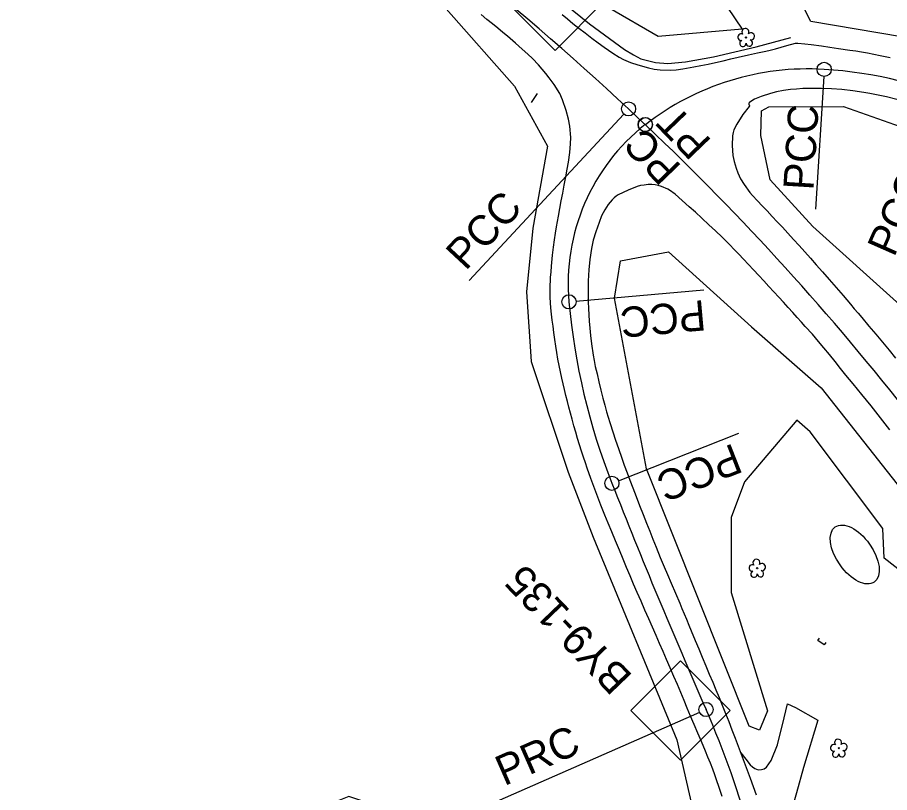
# Model space of a CAD drawing. Extents: x 473158 to 477500, y 500738 to 505114.
# Drawn here: x 475094.4 to 475555.3, y 502314.3 to 502723.9 of the extents above; entities that cross this region are included whole.
import ezdxf

# ---------------------------------------------------------------- set-up
doc = ezdxf.new("R2010")
doc.units = 0
for name, color, linetype in [('CTL Secondary Horizontal and Vertical CELL', 7, 'Continuous'), ('CTL Secondary Horizontal and Vertical Text', 7, 'Continuous'), ('Exist Guardrail', 7, 'Continuous'), ('Exist Horizontal Alignment', 7, 'Continuous'), ('Exist Other Culture Area Outline', 7, 'Continuous'), ('Exist Other Culture Sign', 7, 'Continuous'), ('Exist Roads EOP', 7, 'Continuous'), ('Exist Roads Soil', 7, 'Continuous'), ('Exist Vegetation Tree CELL', 7, 'Continuous'), ('Exist Vegetation Woods Line', 7, 'Continuous')]:
    doc.layers.add(name, color=color, linetype=linetype)

msp = doc.modelspace()

# ---------------------------------------------------------------- linework, layer by layer
at = {"layer": 'CTL Secondary Horizontal and Vertical CELL'}
msp.add_line((475444.73, 502357.61), (475444.73, 502357.61), dxfattribs=at)
for points in [[(475352.26, 502732.72), (475378.47, 502758.92), (475404.72, 502732.67), (475378.52, 502706.47)], [(475418.66, 502357.7), (475444.86, 502383.91), (475471.11, 502357.66), (475444.91, 502331.45)]]:
    msp.add_lwpolyline(points, close=True, dxfattribs=at)
at = {"layer": 'Exist Guardrail'}
msp.add_lwpolyline([(475217.33, 502867.76), (475216.44, 502862.82), (475216.67, 502859.88), (475217.59, 502857.13), (475219.31, 502854.45), (475221.83, 502851.72), (475229.36, 502844.29), (475232.25, 502841.82), (475257.72, 502824.07), (475280.52, 502807.76), (475315.04, 502782.65), (475345.62, 502761.25), (475378.34, 502735.51), (475396.81, 502720.46), (475415.24, 502707), (475419.92, 502704.07), (475423.92, 502701.99), (475431.54, 502699.97), (475438.09, 502699.45), (475447.54, 502700.48), (475462.27, 502702.99), (475484.79, 502708.35), (475503.22, 502713.19)], dxfattribs=at)
at = {"layer": 'Exist Horizontal Alignment'}
for p, q in [((475520.51, 502692.66), (475516.17, 502622.65)), ((475414.82, 502672.8), (475333.05, 502584.93)), ((475389.59, 502573.92), (475457.23, 502580.01)), ((475412.05, 502479.1), (475475.61, 502504.14)), ((475454.89, 502356.7), (475344.98, 502308.44))]:
    msp.add_line(p, q, dxfattribs=at)
for centre in [(475520.74, 502696.41), (475417.37, 502675.55), (475426.16, 502667.3), (475426.3, 502667.17), (475385.86, 502573.59), (475408.56, 502477.72), (475458.32, 502358.2)]:
    msp.add_circle(centre, 3.75, dxfattribs=at)
for centre, radius, start, end in [((474341.25, 501519.13), 1579.67, 47.05976, 56.25321), ((475512.11, 502557.12), 139.55, 86.4527, 127.9451), ((475506.78, 502471.14), 225.7, 66.2091, 86.4527), ((474463.75, 501650.77), 1399.85, 29.91717, 47.05976), ((475492.63, 502583.2), 107.21, 128.3203, 185.1409), ((475730.62, 502604.61), 346.15, 185.1409, 201.5032), ((478543.54, 503712.83), 3369.51, 201.50321, 203.70478), ((475007.6, 502160.31), 492.25, 15.3225, 23.7048)]:
    msp.add_arc(centre, radius, start, end, dxfattribs=at)
at = {"layer": 'Exist Other Culture Area Outline'}
msp.add_lwpolyline([(475521.72, 502393.64), (475520.78, 502392.35), (475517.38, 502394.73), (475518.27, 502395.89)], dxfattribs=at)
msp.add_ellipse((475536.94, 502440.11), major_axis=(-10.33, 14.56), ratio=0.535519, dxfattribs=at)
at = {"layer": 'Exist Other Culture Sign'}
msp.add_line((475369.12, 502683.67), (475365.83, 502678.86), dxfattribs=at)
at = {"layer": 'Exist Roads EOP'}
for points in [[(475466.86, 502312.17), (475465.09, 502317.5), (475464.05, 502320.59), (475462.96, 502323.68), (475461.84, 502326.76), (475460.63, 502329.89), (475459.36, 502333.08), (475458.05, 502336.24), (475455.88, 502341.33), (475454.03, 502345.66), (475452.06, 502350.28), (475450.17, 502354.72), (475448.38, 502358.97), (475446.68, 502363.04), (475444.97, 502367.12), (475443.18, 502371.36), (475441.31, 502375.72), (475439.4, 502380.16), (475437.49, 502384.57), (475435.62, 502388.89), (475433.77, 502393.14), (475431.91, 502397.39), (475430.01, 502401.71), (475428.04, 502406.18), (475426.03, 502410.76), (475423.98, 502415.42), (475421.96, 502420.04), (475420.04, 502424.49), (475418.17, 502428.86), (475416.33, 502433.23), (475414.46, 502437.71), (475412.51, 502442.43), (475410.52, 502447.25), (475408.53, 502452.03), (475406.63, 502456.62), (475404.91, 502460.86), (475402.77, 502466.22), (475401.68, 502469.07), (475399.56, 502474.63), (475397.47, 502480.23), (475395.5, 502485.68), (475394.54, 502488.5), (475393.57, 502491.48), (475392.55, 502494.68), (475391.48, 502498.06), (475390.44, 502501.41), (475389.44, 502504.7), (475388.47, 502508.08), (475387.51, 502511.53), (475386.64, 502514.81), (475385.83, 502517.91), (475385.03, 502521.03), (475384.21, 502524.18), (475383.46, 502527.26), (475382.76, 502530.25), (475382.07, 502533.33), (475381.37, 502536.53), (475380.68, 502539.88), (475380.01, 502543.37), (475379.4, 502546.82), (475378.85, 502550.22), (475378.34, 502553.75), (475377.87, 502557.36), (475377.45, 502560.74), (475377.07, 502563.89), (475376.69, 502567.1), (475376.31, 502570.38), (475375.95, 502575.9), (475375.94, 502580.71), (475376.2, 502586.39), (475376.4, 502589.41), (475376.65, 502592.51), (475377.2, 502598.34), (475377.67, 502602.55), (475378.18, 502606.33), (475378.73, 502609.86), (475379.32, 502613.3), (475380.3, 502618.83), (475381.04, 502622.94), (475381.81, 502627), (475382.59, 502630.98), (475383.39, 502635.18), (475384.21, 502639.57), (475384.96, 502643.69), (475385.62, 502647.4), (475386.4, 502652.55), (475386.71, 502657.07), (475386.78, 502660.41), (475386.29, 502666.36), (475385.55, 502670.17), (475384.36, 502674.67), (475382.54, 502680.28), (475380.99, 502683.6), (475378.07, 502688.38), (475375.41, 502691.98), (475373.64, 502694.2), (475369.85, 502698.75), (475366.53, 502702.24), (475364.09, 502704.5), (475361.15, 502707.14), (475357.67, 502710.22), (475353.36, 502713.89), (475350.89, 502715.96), (475348.24, 502718.16), (475345.45, 502720.45), (475342.53, 502722.84), (475339.47, 502725.33)], [(475382.29, 502725.41), (475385.02, 502723.12), (475387.91, 502720.74), (475391.03, 502718.25), (475394.37, 502715.66), (475397.93, 502712.96), (475401.39, 502710.4), (475404.4, 502708.23), (475409.08, 502705.01), (475412.4, 502702.94), (475414.77, 502701.62), (475418.33, 502700.07), (475422.22, 502698.74), (475427.87, 502697.17), (475430.95, 502696.55), (475434.07, 502696.19), (475439.73, 502696.01), (475442.49, 502696.19), (475446.12, 502696.71), (475451.88, 502697.75), (475455.51, 502698.45), (475459.39, 502699.24), (475463.29, 502700.08), (475467.29, 502700.99), (475471.5, 502701.99), (475475.36, 502702.93), (475480.77, 502704.18), (475485.55, 502705.17), (475489.09, 502705.9), (475491.44, 502706.39), (475495.04, 502707.3), (475497.97, 502708.12), (475500.94, 502708.95), (475505.58, 502710.23), (475506.2, 502710.32), (475506.77, 502710.33), (475510.52, 502709.94), (475513.85, 502709.53), (475519.35, 502708.8), (475523.67, 502708.19), (475528.42, 502707.51), (475534.29, 502706.64), (475537.5, 502706.15), (475540.54, 502705.65), (475543.62, 502705.1), (475546.99, 502704.41), (475550.28, 502703.71), (475555.6, 502702.62)], [(475559.17, 502680.45), (475553.7, 502681.87), (475548.34, 502683.04), (475544.96, 502683.7), (475541.77, 502684.28), (475535.85, 502685.15), (475530.02, 502685.76), (475524.6, 502686.11), (475519.42, 502686.3), (475515.4, 502686.33), (475513.22, 502686.32), (475509.4, 502686.23), (475506.18, 502686.05), (475502.89, 502685.74), (475499.21, 502685.2), (475495.56, 502684.48), (475492.47, 502683.68), (475487.39, 502682.07), (475484.01, 502680.66), (475483.06, 502680.12), (475481.22, 502678.85), (475481, 502678.5), (475480.99, 502678.26), (475481.01, 502677.93), (475481.05, 502677.76), (475481.12, 502677.59), (475481.21, 502677.42), (475481.27, 502677.23), (475481.23, 502676.99), (475481.09, 502676.72), (475477.76, 502672.53), (475474.55, 502667.47), (475473.07, 502664.5), (475472.82, 502663.84), (475472.61, 502663.13), (475472.32, 502661.31), (475472.2, 502656.2), (475472.56, 502650.92), (475473.25, 502647.67), (475474.22, 502644.27), (475475.12, 502641.7), (475476.61, 502638.64), (475478.47, 502635.65), (475481.46, 502631.45), (475482.96, 502629.71), (475485.55, 502626.96), (475487.96, 502624.4), (475490.58, 502621.63), (475493.3, 502618.77), (475496, 502615.89), (475498.7, 502612.98), (475501.52, 502609.89), (475504.48, 502606.62), (475507.47, 502603.31), (475510.47, 502599.98), (475513.46, 502596.62), (475516.49, 502593.21), (475519.81, 502589.45), (475523.41, 502585.34), (475527.07, 502581.14), (475530.75, 502576.89), (475534.64, 502572.35), (475536.66, 502569.96), (475538.69, 502567.57), (475540.66, 502565.24), (475544.44, 502560.78), (475548.07, 502556.47), (475551.61, 502552.21), (475555.07, 502548.03), (475558.49, 502543.9)], [(475555.44, 502505.89), (475552.96, 502509.1), (475550.48, 502512.29), (475548.01, 502515.46), (475545.54, 502518.58), (475543.1, 502521.64), (475540.69, 502524.63), (475538.3, 502527.54), (475536.05, 502530.28), (475532.29, 502534.87), (475529.37, 502538.45), (475526.49, 502542.04), (475523.53, 502545.75), (475520.63, 502549.3), (475517.76, 502552.71), (475514.51, 502556.44), (475510.79, 502560.57), (475508.72, 502562.86), (475506.53, 502565.31), (475504.19, 502567.92), (475501.76, 502570.63), (475499.28, 502573.37), (475496.75, 502576.14), (475494.17, 502578.94), (475491.55, 502581.77), (475488.89, 502584.63), (475486.2, 502587.52), (475483.48, 502590.44), (475480.78, 502593.31), (475478.16, 502596.08), (475475.63, 502598.74), (475473.18, 502601.3), (475470.86, 502603.68), (475466.77, 502607.76), (475463.3, 502611.04), (475459.77, 502614.34), (475456.13, 502617.73), (475452.69, 502620.9), (475449.41, 502623.86), (475445.78, 502627.08), (475441.94, 502630.42), (475439.1, 502632.6), (475438.13, 502633.18), (475434.78, 502634.6), (475433.09, 502635.12), (475431.47, 502635.45), (475429.74, 502635.59), (475427.72, 502635.54), (475425.61, 502635.33), (475423.64, 502634.98), (475421.93, 502634.54), (475417.23, 502632.62), (475411.88, 502630.08), (475410.81, 502629.41), (475409.73, 502628.57), (475408.67, 502627.55), (475406.64, 502625.04), (475404.78, 502622.18), (475403.15, 502619.03), (475401.77, 502615.5), (475400.03, 502610.62), (475398.72, 502606.26), (475397.77, 502601.81), (475396.9, 502596.03), (475396.33, 502590.52), (475396.16, 502587.62), (475396.06, 502584.44), (475396, 502580.86), (475396, 502577.15), (475396.05, 502573.57), (475396.16, 502570.11), (475396.33, 502566.73), (475396.57, 502563.32), (475396.87, 502559.77), (475397.27, 502555.85), (475397.8, 502551.34), (475398.62, 502545.41), (475399.11, 502542.64), (475399.8, 502539.4), (475400.71, 502535.53), (475401.71, 502531.31), (475402.78, 502526.87), (475403.83, 502522.71), (475404.85, 502518.92), (475405.77, 502515.55), (475407.42, 502509.85), (475409.19, 502504.34), (475410.28, 502501.08), (475412.19, 502495.51), (475413.6, 502491.49), (475415.08, 502487.38), (475416.57, 502483.31), (475418.02, 502479.4), (475419.56, 502475.33), (475421.33, 502470.8), (475423.2, 502466.03), (475425.07, 502461.25), (475426.87, 502456.65), (475428.56, 502452.42), (475430.2, 502448.29), (475431.9, 502443.97), (475434.1, 502438.45), (475436.16, 502433.56), (475437.93, 502429.46), (475439.89, 502424.94), (475442.16, 502419.63), (475444.43, 502414.32), (475445.57, 502411.61), (475446.75, 502408.79), (475447.97, 502405.86), (475449.21, 502402.82), (475450.43, 502399.84), (475452.59, 502394.61), (475454.44, 502390.2), (475456.3, 502385.8), (475458.21, 502381.31), (475460.06, 502376.92), (475461.83, 502372.67), (475463.54, 502368.57), (475465.19, 502364.58), (475466.86, 502360.46), (475468.57, 502356.18), (475470.3, 502351.82), (475472.04, 502347.43), (475473.73, 502343.1), (475475.34, 502338.85), (475476.95, 502334.59), (475478.55, 502330.33), (475480.12, 502326.12), (475481.64, 502321.92), (475483.2, 502317.55), (475484.78, 502313.06)]]:
    msp.add_lwpolyline(points, dxfattribs=at)
at = {"layer": 'Exist Roads Soil'}
msp.add_lwpolyline([(475476.71, 502335.29), (475479.28, 502331.91), (475481.59, 502329.05), (475482.85, 502327.84), (475484.2, 502327.08), (475485.85, 502326.42), (475487.62, 502326.45), (475489.07, 502326.88), (475490.2, 502327.82), (475492.83, 502331.2), (475496.1, 502339.6), (475499.62, 502353.76), (475501.41, 502361.15), (475505.61, 502359.29), (475517.48, 502352.5), (475509.78, 502327.56), (475506.16, 502314.15), (475504.1, 502306.86), (475502.79, 502299.95), (475502.25, 502290.94), (475500.28, 502283.72), (475497.91, 502279.11), (475494.63, 502278.17)], dxfattribs=at)
at = {"layer": 'Exist Vegetation Tree CELL'}
for p, q in [((475479.49, 502713.28), (475479.49, 502713.28)), ((475485.37, 502432.85), (475485.37, 502432.85)), ((475528.51, 502337.78), (475528.51, 502337.78))]:
    msp.add_line(p, q, dxfattribs=at)
for centre in [(475479.49, 502713.28), (475485.37, 502432.85), (475528.51, 502337.78)]:
    msp.add_circle(centre, 0.326, dxfattribs=at)
for centre, radius, start, end in [((475479.11, 502716.16), 1.86, 330.1651, 219.7134), ((475476.89, 502713.44), 1.73, 62.6636, 279.3457), ((475482.04, 502713.87), 1.9, 257.1011, 134.1999), ((475477.79, 502710.16), 1.69, 111.5671, 6.231), ((475481.17, 502710.38), 1.7, 181.2822, 74.56), ((475484.99, 502435.73), 1.86, 330.1651, 219.7134), ((475482.77, 502433.01), 1.73, 62.6636, 279.3457), ((475483.67, 502429.73), 1.69, 111.5671, 6.231), ((475487.05, 502429.96), 1.7, 181.2822, 74.56), ((475487.92, 502433.44), 1.9, 257.1011, 134.1999), ((475525.9, 502337.93), 1.73, 62.6636, 279.3457), ((475528.12, 502340.65), 1.86, 330.1651, 219.7134), ((475531.06, 502338.37), 1.9, 257.1011, 134.1999), ((475526.8, 502334.66), 1.69, 111.5671, 6.231), ((475530.18, 502334.88), 1.7, 181.2822, 74.56)]:
    msp.add_arc(centre, radius, start, end, dxfattribs=at)
at = {"layer": 'Exist Vegetation Woods Line'}
for points in [[(475697.4, 502727.92), (475688.86, 502696.09), (475686, 502663.11), (475652.17, 502674.74), (475599.58, 502703.42), (475587.38, 502718.1), (475582.11, 502744.06), (475561.68, 502713.66), (475513.63, 502721.78), (475505.24, 502738.53), (475493.85, 502754.4), (475471.86, 502759.83), (475461.5, 502741.2), (475477.48, 502717.68), (475433.11, 502713.77), (475407.41, 502728.53), (475369.2, 502759.84), (475334.77, 502792.14), (475288.78, 502817.79), (475268.13, 502832.08), (475231.22, 502863.61), (475223.58, 502870.17), (475227.24, 502912), (475230.74, 502956.28)], [(475094.38, 502883.41), (475147.35, 502853.58), (475167.9, 502821.85), (475191.94, 502797.5), (475215.72, 502771.8), (475254.69, 502766.43), (475320.94, 502728.35), (475357.01, 502687.58), (475374.45, 502655.84), (475366.77, 502612.6), (475363.45, 502578.81), (475365.9, 502542.13), (475385.44, 502483.6), (475398.73, 502449.23)], [(475560.77, 502571.96), (475514.76, 502613.46), (475492.24, 502638.09), (475487.3, 502661.49), (475487.62, 502674.6), (475491.52, 502676.65), (475531.03, 502676.82), (475575.86, 502660.99), (475636.13, 502637.63), (475673.71, 502619.9)], [(475426.9, 502485.3), (475409.86, 502575.47), (475413.15, 502595.29), (475438.52, 502600.07), (475482.31, 502560.32), (475519.21, 502528.11)], [(475519.21, 502528.11), (475566.55, 502468.17), (475627.31, 502380.99), (475623.71, 502375.33), (475570.95, 502423.65), (475552.52, 502438.18), (475551.71, 502453.86), (475513.44, 502504.97), (475506.23, 502511.15), (475478.72, 502478.44), (475471.69, 502459.66), (475471.56, 502419.97), (475490.82, 502357.44), (475486.63, 502347.37), (475481.08, 502349.43), (475426.9, 502485.3)], [(475398.73, 502449.23), (475442.9, 502342.11), (475450.77, 502307.49), (475390.78, 502274.13), (475372.41, 502263.9), (475334.31, 502256.89), (475319.24, 502273.44), (475291.09, 502305.03), (475269.5, 502312.26), (475240.44, 502300.6)]]:
    msp.add_lwpolyline(points, dxfattribs=at)

# ---------------------------------------------------------------- texts
at = {"layer": 'CTL Secondary Horizontal and Vertical Text'}
msp.add_text('BY9-135', height=16, rotation=133.8723, dxfattribs=at).set_placement((475420.06, 502375.91))
at = {"layer": 'Exist Horizontal Alignment'}
for s, rotation, p in [('PCC', 86.4527, (475515.09, 502632.28)), ('PT', 133.8722, (475461.77, 502658.61)), ('PC', 133.8722, (475445.93, 502645.12)), ('PCC', 66.2091, (475557.7, 502596.76)), ('PCC', 47.0598, (475331.24, 502589.64)), ('PCC', 185.1409, (475457.4, 502574.57)), ('PCC', 201.5032, (475472.85, 502499.03)), ('PRC', 23.7048, (475351.64, 502317.63))]:
    msp.add_text(s, height=16, rotation=rotation, dxfattribs=at).set_placement(p)

doc.saveas('drawing.dxf')
